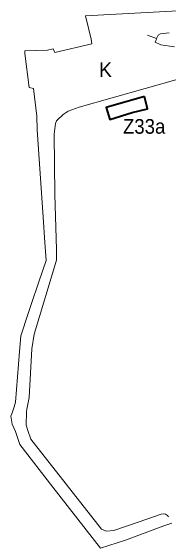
# Model space of a CAD drawing. Extents: x -650276 to -642489, y -1074311 to -1066658.
# Drawn here: x -644494 to -644235, y -1070907 to -1070024 of the extents above; entities that cross this region are included whole.
import ezdxf

# ---------------------------------------------------------------- set-up
doc = ezdxf.new("R2010")
doc.units = 0
doc.header["$LTSCALE"] = 9.6
for name, color, linetype, lineweight in [('45', 7, 'Continuous', 40), ('46', 7, 'Continuous', 13), ('47', 7, 'Continuous', 13), ('48', 7, 'Continuous', 35)]:
    doc.layers.add(name, color=color, linetype=linetype, lineweight=lineweight)

msp = doc.modelspace()

# ---------------------------------------------------------------- linework, layer by layer
at = {"layer": '45'}
msp.add_lwpolyline([(-644274.246, -1070164.59), (-644337.256, -1070182.64), (-644331.096, -1070202.4), (-644294.206, -1070190.9), (-644269.036, -1070184.57)], close=True, dxfattribs=at)
msp.add_lwpolyline([(-644274.246, -1070164.59), (-644337.256, -1070182.64), (-644331.096, -1070202.4), (-644294.206, -1070190.9), (-644269.036, -1070184.57)], close=True, dxfattribs=at)
at = {"layer": '47'}
for points in [[(-644219.33, -1070023.53), (-644370.87, -1070032.13), (-644361.74, -1070070.32), (-644361.55, -1070070.345), (-644360.41, -1070077.91), (-644421.26, -1070091.99), (-644423.99, -1070086.17), (-644433.19, -1070088.37), (-644470.17, -1070089.43), (-644470.55, -1070093.61), (-644463.28, -1070149.42), (-644456.41, -1070151.18), (-644450.72, -1070196.97), (-644450.15, -1070219.06), (-644445.28, -1070290.84), (-644440.36, -1070362.62), (-644437.53, -1070404.1), (-644435.51, -1070433.85), (-644447.14, -1070467.28), (-644460.5, -1070507.68), (-644464.98, -1070521.13), (-644476.94, -1070557.45), (-644479.06, -1070583.13), (-644485.64, -1070666.7), (-644488.01, -1070674.2), (-644491.691, -1070685.524), (-644491.82, -1070685.92), (-644493.5, -1070689.75), (-644491.42, -1070702.64), (-644485.61, -1070714.95), (-644478.67, -1070736.28), (-644424.37, -1070806.03), (-644346.21, -1070906.61), (-644305.07, -1070893.39), (-644242.29, -1070869.82), (-644229.12, -1070865.52)], [(-644225.13, -1070082.95), (-644247.3, -1070079.69), (-644256.54, -1070075.02), (-644255.52, -1070072.5), (-644254.136, -1070069.079), (-644254.13, -1070069.08), (-644254.25, -1070069.37), (-644269.156, -1070063.55), (-644254.25, -1070069.37), (-644251.9, -1070063.55), (-644248.05, -1070061.33), (-644233.51, -1070059.54)], [(-644399.15, -1070188.55), (-644381.21, -1070181.71), (-644218.65, -1070135.75)], [(-644243.15, -1070849.89), (-644246.93, -1070850.52), (-644282.77, -1070863.19), (-644324.34, -1070877.71), (-644337.15, -1070878.64), (-644344.86, -1070875.09), (-644460.82, -1070727.21), (-644465.31, -1070713.25), (-644468.1, -1070704.23), (-644467.84, -1070682.37), (-644466.998, -1070678.065), (-644463.28, -1070659.06), (-644458.85, -1070579.04), (-644455.2, -1070554.88), (-644418.69, -1070433.36), (-644418.23, -1070415.62), (-644421.45, -1070325.29), (-644422.5, -1070226.42), (-644420.14, -1070208.56), (-644418.61, -1070204.51), (-644417.36, -1070203.24), (-644407.55, -1070194.16), (-644399.15, -1070188.55)], [(-644234.66, -1070855.08), (-644236.3, -1070852.87), (-644239.47, -1070850.71), (-644243.15, -1070849.89)]]:
    msp.add_lwpolyline(points, dxfattribs=at)

# ---------------------------------------------------------------- texts
at = {"layer": '46', "width": 0.95}
msp.add_text('Z33a', height=24, dxfattribs=at).set_placement((-644309.424, -1070225.565))
msp.add_text('Z33a', height=24, dxfattribs=at).set_placement((-644309.424, -1070225.565))
at = {"layer": '48'}
msp.add_text('K', height=24, dxfattribs=at).set_placement((-644348.839, -1070132.426))

doc.saveas('drawing.dxf')
